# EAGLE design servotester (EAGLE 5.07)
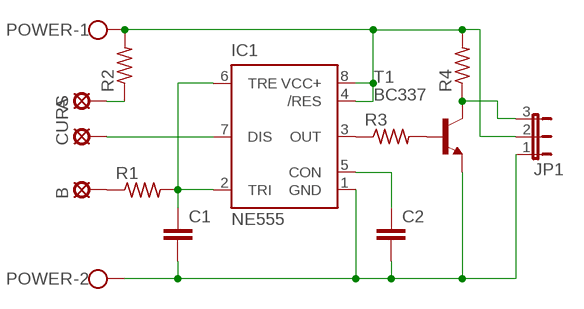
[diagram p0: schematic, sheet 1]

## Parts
A  SE14  [SE14]
B  SE14  [SE14]
C1  C-EU050-025X075  [C050-025X075]
C2  C-EU050-025X075  [C050-025X075]
CURS  SE14  [SE14]
IC1  NE555  [DIL-08]
JP1  JP2E  [JP2]
POWER  W237-102  [W237-102]
R1  R-US_0207/10  [0207/10]
R2  R-US_0207/10  [0207/10]
R3  R-US_0207/10  [0207/10]
R4  R-US_0207/10  [0207/10]
T1  BC337  [TO92]

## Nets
N$1: IC1.3(OUT) R3.1
N$2: R3.2 T1.2(B)
N$3: C2.1 IC1.5(CON)
N$4: C1.2 C2.2 IC1.1(GND) JP1.1 POWER.2 T1.1(E)
N$5: C1.1 IC1.2(TRI) IC1.6(TRE) R1.2
N$6: B.MP R1.1
N$8: A.MP R2.1
N$9: CURS.MP IC1.7(DIS)
N$10: IC1.4(/RES) IC1.8(VCC+) JP1.2 POWER.1 R2.2 R4.2
N$11: JP1.3 R4.1 T1.3(C)

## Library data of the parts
A B CURS = solpad:SE14: SOLDER PAD
C1 C2 = resistor:C-EU: CAPACITOR, European symbol
IC1 = st-microelectronics:NE555: General purpose bipolar Timer
JP1 = jumper:JP2E: JUMPER
POWER = con-wago-500:W237-102: WAGO SCREW CLAMP
R1-R4 = resistor:R-US_: RESISTOR, American symbol
T1 = transistor:BC337: NPN TRANSISTOR

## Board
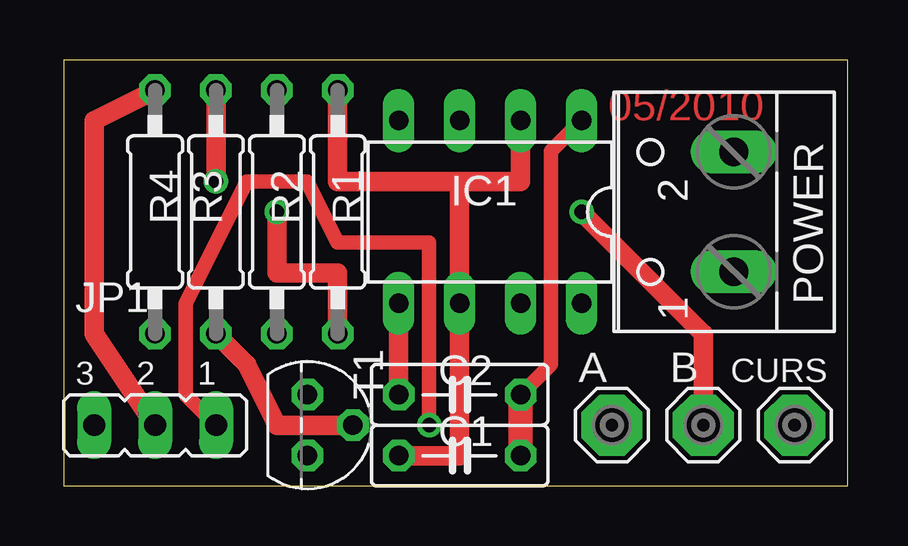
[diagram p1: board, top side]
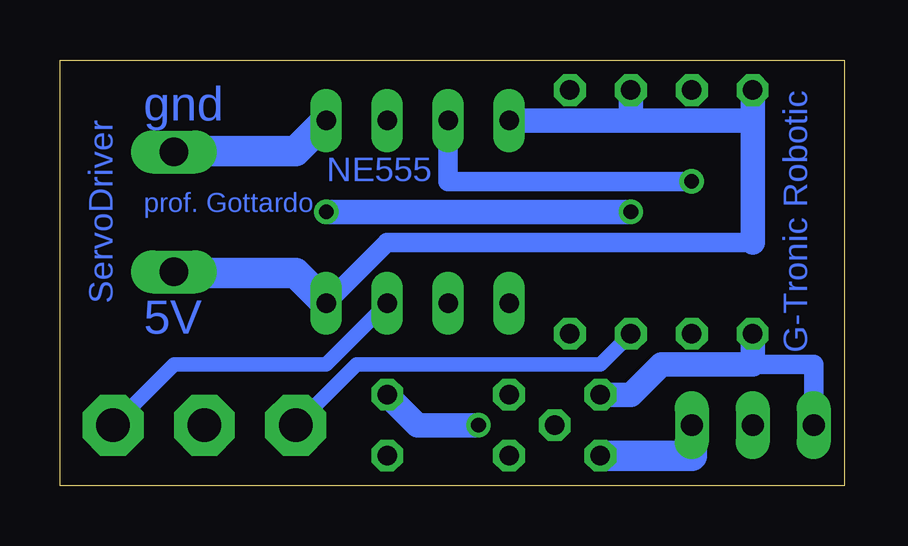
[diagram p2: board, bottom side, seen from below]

Size 32.69 x 17.77 mm. Coordinates in mm from the lower left corner, seen from the top.
Outline: 0,0 32.69,0 32.69,17.77 0,17.77 0,0
Copper layers (1*16): Top 0.035mm / dielectric 1.5mm / Bottom 0.035mm
Design rules "default": minimum track width 10mil, minimum drill 24mil, track to track 8mil, track to pad 8mil, pad to pad 8mil, via to via 8mil, smd to smd 8mil, copper to edge 40mil, drill to drill 8mil, minimum pad ring 10mil, minimum via ring 8mil, stop-mask expansion 4mil, vias tented up to drill 0mil, thermal gap 10mil

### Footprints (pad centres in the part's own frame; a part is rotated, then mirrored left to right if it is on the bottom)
SE14 = drill 1.397 pad 2.54 octagon: MP 0,0
C050-025X075 = drill 0.813 octagon: 1 -2.54,0; 2 2.54,0
DIL-08 = drill 0.813 long: 1 -3.81,-3.81; 2 -1.27,-3.81; 3 1.27,-3.81; 4 3.81,-3.81; 5 3.81,3.81; 6 1.27,3.81; 7 -1.27,3.81; 8 -3.81,3.81
JP2 = drill 0.914 long: 1 -2.54,0; 2 0,0; 3 2.54,0
W237-102 = drill 1.194 long: 1 -2.5,-1.27; 2 2.5,-1.27
0207/10 = drill 0.813 octagon: 1 -5.08,0; 2 5.08,0
TO92 = drill 0.813 octagon: 1 1.27,0; 2 0,1.905; 3 -1.27,0

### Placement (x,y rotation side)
A  22.86,2.54 0 top
B  26.67,2.54 0 top
C1  16.51,1.27 0 top
C2  16.51,3.81 0 top
CURS  30.48,2.54 0 top
IC1  17.78,11.43 180 top
JP1  3.81,2.54 180 top
POWER  26.67,11.43 90 top
R1  11.43,11.43 90 top
R2  8.89,11.43 90 top
R3  6.35,11.43 270 top
R4  3.81,11.43 90 top
T1  10.16,2.54 270 top

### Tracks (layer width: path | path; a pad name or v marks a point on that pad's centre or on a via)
N$1  (via drill 0.61)
  Top 0.813: v6.35,12.7 R3.1
  Bottom 0.813: v6.35,12.7 16.51,12.7 IC1.3
N$2
  Top 0.813: R3.2 7.62,5.08 8.89,2.54 T1.2
N$3
  Top 0.813: C2.1 IC1.5
N$4  (via drill 0.61)
  Top 0.61: C2.2 20.32,5.08 20.32,13.97 IC1.1 | JP1.1 5.08,3.81 5.08,7.62 7.62,12.7 10.16,12.7 11.43,10.16 15.24,10.16 v15.24,2.54
  Top 1.016: C2.2 C1.2
  Bottom 0.254: 27.94,13.97 POWER.2
  Bottom 1.016: v15.24,2.54 17.78,2.54 C2.2
  Bottom 1.27: T1.1 6.35,1.27 JP1.1 | IC1.1 22.86,13.97 27.94,13.97
N$5
  Top 0.813: C1.1 16.51,1.27 IC1.6 16.51,12.7 | R1.2 11.43,12.7 16.51,12.7 | 16.51,12.7 19.05,12.7 IC1.2
N$6  (via drill 0.61)
  Top 0.813: R1.1 11.43,8.89 8.89,8.89 v8.89,11.43 | v21.59,11.43 26.67,6.35 B.MP
  Bottom 1.016: v8.89,11.43 v21.59,11.43
N$8
  Bottom 0.61: R2.1 10.16,5.08 20.32,5.08 A.MP
N$9
  Bottom 0.61: IC1.7 21.59,5.08 27.94,5.08 CURS.MP
N$10
  Top 0.813: JP1.2 1.27,6.35 1.27,15.24 R4.2
  Bottom 0.254: 27.94,8.89 POWER.1
  Bottom 0.813: IC1.8 19.05,10.16 3.81,10.16
  Bottom 1.016: 8.89,15.24 IC1.4 | 8.89,15.24 3.81,15.24 R4.2 3.81,10.16 | 8.89,15.24 R2.2
  Bottom 1.27: IC1.8 22.86,8.89 27.94,8.89
N$11
  Bottom 0.813: JP1.3 1.27,5.08 3.81,5.08
  Bottom 1.016: T1.3 8.89,3.81 7.62,5.08 3.81,5.08 R4.1

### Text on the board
Top: 05/2010
Bottom: G-Tronic Robotic | gnd | NE555 | prof. Gottardo | ServoDriver | 5V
